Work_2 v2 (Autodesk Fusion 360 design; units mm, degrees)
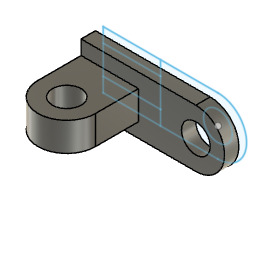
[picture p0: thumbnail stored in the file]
sketch "Sketch1" plane through (0, 0, 0) normal (0, 1, 0) x axis (1, 0, 0)
  line L1 (110, -30) -> (30, -30)
  line L2 (30, -70) -> (30, -30)
  line L3 (110, -70) -> (30, -70)
  line L4 (70, -40) -> (30, -40)
  line L5 (70, -60) -> (30, -60)
  line L6 (70, -70) -> (70, -60)
  line L7 (70, -30) -> (70, -40)
  line L8 (70, -60) -> (70, -40)
  arc A1 centre (110, -50) radius 20 clockwise from (110, -30) to (110, -70)
  circle C1 centre (110, -50) radius 10
  point P8 (30, -40)
  point P10 (30, -60)
  point P12 (70, -70)
  point P13 (70, -30)
  point P9 (70, -40)
  point P11 (70, -60)
  horizontal L1
  perpendicular L1 L2
  perpendicular L2 L3
  tangent L3 A1
  tangent L1 A1
  concentric A1 C1
  coincident L2 P8
  horizontal L4
  coincident L2 P10
  perpendicular L2 L5
  midpoint L3 P12
  perpendicular L3 L6
  midpoint L1 P13
  perpendicular L1 L7
  perpendicular L5 L8
  dimension "d1" distance P9 P13 = 10
  dimension "d2" distance P8 P9 = 40
  dimension "d3" distance P9 P11 = 20
  dimension "d4" distance P11 P12 = 10
extrude "Extrude1" new body sketch "Sketch1" along normal blind 10
extrude "Extrude2" add sketch "Sketch1" profile of L2 L4 L5 L8 against normal blind 30
sketch "Sketch2" plane through (0, 0, 40) normal (0, 0, -1) x axis (1, 0, 0)
  line L1 (70, 0) -> (30, 0)
  line L2 (70, 30) -> (70, 0)
  line L3 (30, 30) -> (70, 30)
  line L4 (30, 0) -> (30, 30)
  circle C1 centre (50, 30) radius 10
  arc A1 centre (50, 30) radius 20 clockwise from (30, 30) to (70, 30)
  point P6 (50, 30)
  point P4 (70, 30)
  point P8 (70, 30)
  point P5 (30, 30)
  point P7 (30, 30)
  midpoint L3 P6
  tangent L4 A1
  coincident P4 P8
  coincident P5 P7
extrude "Extrude3" add sketch "Sketch2" profile of L3 C1 A1 against normal blind 20
sketch "Sketch3" plane through (0, 0, 0) normal (0, 0, 1) x axis (1, 0, 0)
  line L1 (60, -30) -> (40, -30)
  arc A1 centre (50, -30) radius 10 clockwise from (40, -30) to (60, -30)
  point P4 (50, -30)
  horizontal L1
  midpoint P4 L1
move "Move1"
extrude "Extrude4" cut sketch "Sketch3" along normal blind 20
move "Move2"
move "Move3"
move "Move4"
move "Move5"
move "Move6"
